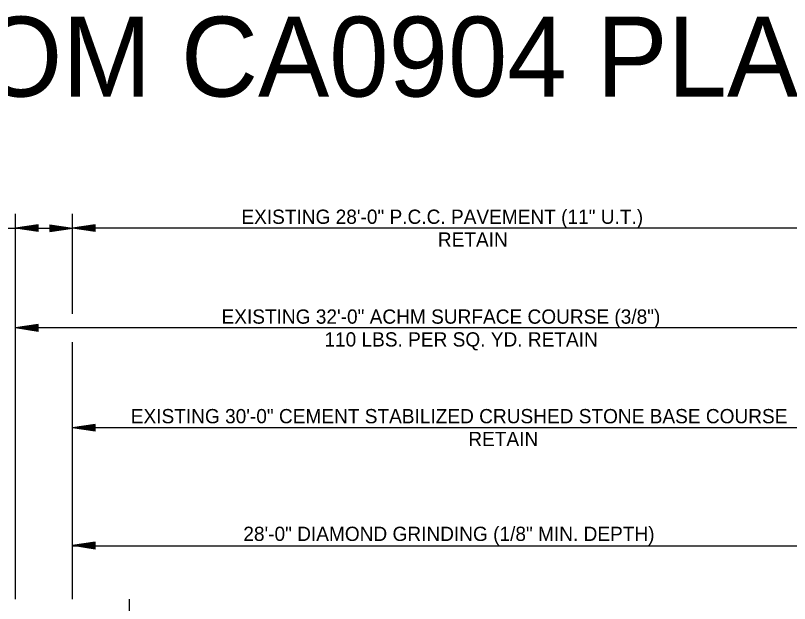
# Model space of a CAD drawing. Extents: x 60325 to 61047, y 53669 to 53767.
# Drawn here: x 60351.25 to 60378.39, y 53746.19 to 53766.8 of the extents above; entities that cross this region are included whole.
import ezdxf

# ---------------------------------------------------------------- set-up
doc = ezdxf.new("R2010")
doc.units = 0
for name, color, linetype in [('Level 63', 7, 'Continuous'), ('R_Border', 7, 'Continuous'), ('R_Border Prem', 7, 'Continuous')]:
    doc.layers.add(name, color=color, linetype=linetype)

msp = doc.modelspace()

# ---------------------------------------------------------------- linework, layer by layer
at = {"layer": 'R_Border'}
for p, q in [((60353.247, 53746.34), (60353.247, 53748.698)), ((60354.047, 53748.338), (60353.247, 53748.218)), ((60354.047, 53748.318), (60353.38, 53748.218)), ((60354.047, 53748.297), (60353.518, 53748.218)), ((60354.047, 53748.277), (60353.651, 53748.218)), ((60354.047, 53748.257), (60353.787, 53748.218)), ((60354.047, 53748.237), (60353.92, 53748.218)), ((60354.047, 53748.098), (60354.047, 53748.338)), ((60354.047, 53748.098), (60353.247, 53748.218)), ((60381.247, 53748.198), (60353.247, 53748.198)), ((60354.047, 53748.118), (60353.38, 53748.218)), ((60354.047, 53748.138), (60353.518, 53748.218)), ((60354.047, 53748.158), (60353.651, 53748.218)), ((60354.047, 53748.179), (60353.787, 53748.218)), ((60354.047, 53748.199), (60353.92, 53748.218)), ((60355.247, 53741.845), (60355.247, 53746.34))]:
    msp.add_line(p, q, dxfattribs=at)
at = {"layer": 'R_Border Prem'}
for p, q in [((60351.247, 53746.34), (60351.247, 53759.845)), ((60353.247, 53756.345), (60353.247, 53759.845)), ((60352.047, 53759.465), (60351.247, 53759.345)), ((60352.047, 53759.445), (60351.38, 53759.345)), ((60352.047, 53759.424), (60351.518, 53759.345)), ((60352.047, 53759.404), (60351.651, 53759.345)), ((60352.047, 53759.384), (60351.787, 53759.345)), ((60352.047, 53759.363), (60351.92, 53759.345)), ((60352.047, 53759.225), (60352.047, 53759.465)), ((60352.447, 53759.465), (60353.247, 53759.345)), ((60352.447, 53759.465), (60352.447, 53759.225)), ((60352.447, 53759.445), (60353.113, 53759.345)), ((60352.447, 53759.424), (60352.975, 53759.345)), ((60352.447, 53759.404), (60352.842, 53759.345)), ((60352.447, 53759.383), (60352.707, 53759.345)), ((60352.447, 53759.363), (60352.573, 53759.345)), ((60354.047, 53759.465), (60353.247, 53759.345)), ((60354.047, 53759.445), (60353.38, 53759.345)), ((60354.047, 53759.424), (60353.518, 53759.345)), ((60354.047, 53759.404), (60353.651, 53759.345)), ((60354.047, 53759.384), (60353.787, 53759.345)), ((60354.047, 53759.363), (60353.92, 53759.345)), ((60354.047, 53759.225), (60354.047, 53759.465)), ((60344.933, 53759.345), (60353.247, 53759.345)), ((60352.047, 53759.225), (60351.247, 53759.345)), ((60352.047, 53759.245), (60351.38, 53759.345)), ((60352.047, 53759.265), (60351.518, 53759.345)), ((60352.047, 53759.285), (60351.651, 53759.345)), ((60352.047, 53759.306), (60351.787, 53759.345)), ((60352.047, 53759.326), (60351.92, 53759.345)), ((60352.447, 53759.225), (60353.247, 53759.345)), ((60352.447, 53759.305), (60352.707, 53759.345)), ((60352.447, 53759.265), (60352.975, 53759.345)), ((60352.447, 53759.245), (60353.113, 53759.345)), ((60352.447, 53759.285), (60352.842, 53759.345)), ((60352.447, 53759.326), (60352.573, 53759.345)), ((60381.247, 53759.345), (60353.247, 53759.345)), ((60354.047, 53759.225), (60353.247, 53759.345)), ((60354.047, 53759.245), (60353.38, 53759.345)), ((60354.047, 53759.265), (60353.518, 53759.345)), ((60354.047, 53759.285), (60353.651, 53759.345)), ((60354.047, 53759.306), (60353.787, 53759.345)), ((60354.047, 53759.326), (60353.92, 53759.345)), ((60352.047, 53755.965), (60351.247, 53755.845)), ((60383.247, 53755.845), (60351.247, 53755.845)), ((60352.047, 53755.725), (60351.247, 53755.845)), ((60352.047, 53755.945), (60351.38, 53755.845)), ((60352.047, 53755.745), (60351.38, 53755.845)), ((60352.047, 53755.924), (60351.518, 53755.845)), ((60352.047, 53755.765), (60351.518, 53755.845)), ((60352.047, 53755.904), (60351.651, 53755.845)), ((60352.047, 53755.785), (60351.651, 53755.845)), ((60352.047, 53755.884), (60351.787, 53755.845)), ((60352.047, 53755.806), (60351.787, 53755.845)), ((60352.047, 53755.863), (60351.92, 53755.845)), ((60352.047, 53755.826), (60351.92, 53755.845)), ((60352.047, 53755.725), (60352.047, 53755.965)), ((60353.247, 53748.698), (60353.247, 53755.345)), ((60354.047, 53752.465), (60353.247, 53752.345)), ((60383.247, 53752.345), (60353.247, 53752.345)), ((60354.047, 53752.225), (60353.247, 53752.345)), ((60354.047, 53752.445), (60353.38, 53752.345)), ((60354.047, 53752.245), (60353.38, 53752.345)), ((60354.047, 53752.424), (60353.518, 53752.345)), ((60354.047, 53752.265), (60353.518, 53752.345)), ((60354.047, 53752.404), (60353.651, 53752.345)), ((60354.047, 53752.285), (60353.651, 53752.345)), ((60354.047, 53752.384), (60353.787, 53752.345)), ((60354.047, 53752.306), (60353.787, 53752.345)), ((60354.047, 53752.363), (60353.92, 53752.345)), ((60354.047, 53752.326), (60353.92, 53752.345)), ((60354.047, 53752.225), (60354.047, 53752.465))]:
    msp.add_line(p, q, dxfattribs=at)

# ---------------------------------------------------------------- texts
at = {"layer": 'Level 63'}
msp.add_text('FROM CA0904 PLANS', height=2.8, dxfattribs=at).set_placement((60344.986, 53763.958))
at = {"layer": 'R_Border'}
msp.add_text('28\'-0" DIAMOND GRINDING (1/8" MIN. DEPTH)', height=0.5, dxfattribs=at).set_placement((60359.237, 53748.38))
at = {"layer": 'R_Border Prem'}
for s, p in [('EXISTING 28\'-0" P.C.C. PAVEMENT (11" U.T.)', (60359.169, 53759.495)), ('RETAIN', (60366.059, 53758.695)), ('EXISTING 32\'-0" ACHM SURFACE COURSE (3/8")', (60358.473, 53755.995)), ('110 LBS. PER SQ. YD. RETAIN', (60362.081, 53755.195)), ('EXISTING 30\'-0" CEMENT STABILIZED CRUSHED STONE BASE COURSE', (60355.291, 53752.505)), ('RETAIN', (60367.127, 53751.705))]:
    msp.add_text(s, height=0.5, dxfattribs=at).set_placement(p)

doc.saveas('drawing.dxf')
